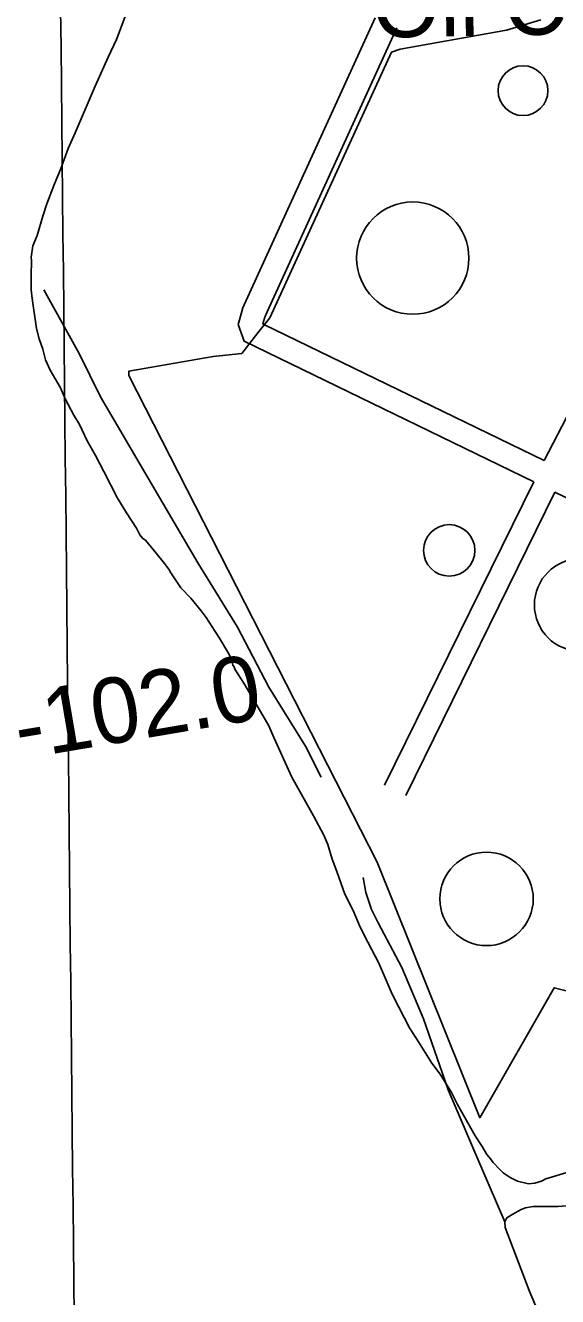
# Model space of a CAD drawing. Extents: x 3625074 to 3663148, y 511451 to 537151.
# Drawn here: x 3655631 to 3656305, y 518099 to 519708 of the extents above; entities that cross this region are included whole.
import ezdxf

# ---------------------------------------------------------------- set-up
doc = ezdxf.new("R2010")
doc.units = 0
for name, color, linetype in [('V-BLDG-IDEN', 7, 'Continuous'), ('V-DOMW-TANK', 7, 'Continuous'), ('V-GRID-MAJR', 7, 'Continuous'), ('V-RIVR-RANG-IDEN', 7, 'Continuous'), ('V-ROAD-CNTR', 7, 'Continuous'), ('V-SITE-OTLN', 7, 'Continuous'), ('V-SITE-VEGE', 7, 'Continuous'), ('V-TOPO-SHOR', 7, 'Continuous')]:
    doc.layers.add(name, color=color, linetype=linetype)

msp = doc.modelspace()

# ---------------------------------------------------------------- linework, layer by layer
at = {"layer": 'V-DOMW-TANK'}
for centre, radius in [((3656260.8533878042, 519625.75441761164), 31.546175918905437), ((3656121.260359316, 519413.65974637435), 71.10281345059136), ((3656167.4155102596, 519043.55996418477), 32.58380201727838), ((3656334.055766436, 518974.54792726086), 58.795414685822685), ((3656214.6349138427, 518602.2098070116), 59.181858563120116)]:
    msp.add_circle(centre, radius, dxfattribs=at)
at = {"layer": 'V-GRID-MAJR'}
msp.add_spline([(3655702.349, 517124.989), (3655639.7800000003, 523183.706), (3655577.191, 529244.355), (3655514.6010000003, 535305.018), (3655514.5810000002, 535306.936)], degree=3, dxfattribs=at)
at = {"layer": 'V-ROAD-CNTR'}
for points in [[(3655905.873, 519349.808), (3656073.653, 519717.962)], [(3655936.9050000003, 519345.561), (3656100.951, 519705.522)], [(3656287.5700000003, 519157.31200000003), (3656400.1684689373, 519374.43589152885), (3656417.7275075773, 519374.50241756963)], [(3656274.34, 519130.387), (3655907.691, 519308.363), (3655900.017, 519329.52400000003), (3655905.589, 519349.185), (3655905.873, 519349.808)], [(3656287.571, 519157.313), (3655931.7430000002, 519330.03500000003), (3655931.519, 519330.65400000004), (3655933.8310000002, 519338.815), (3655936.9050000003, 519345.561)], [(3656085.5700000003, 518746.238), (3656274.339, 519130.38800000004)], [(3656112.494, 518733.00800000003), (3656301.328, 519117.287)], [(3656531.8680000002, 519005.38), (3656301.328, 519117.287)]]:
    msp.add_lwpolyline(points, dxfattribs=at)
at = {"layer": 'V-SITE-OTLN'}
msp.add_lwpolyline([(3657238.198, 519920.066), (3657108.16, 519613.574), (3657087.029, 519593.178), (3657053.732, 519589.613), (3656946.394, 519627.511), (3656383.164, 518471.54600000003), (3656383.117, 518468.77900000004), (3656300.4020000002, 518489.626), (3656206.106, 518325.128), (3656076.1210000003, 518648.675), (3655761.606, 519264.886), (3655761.704, 519270.424), (3655868.659, 519289.304), (3655904.724, 519292.82), (3655925.286, 519318.99), (3655940.1380000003, 519337.891), (3656094.248, 519674.418), (3656105.396, 519678.375), (3656240.136, 519702.304), (3656283.291, 519715.38800000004)], dxfattribs=at)
at = {"layer": 'V-SITE-VEGE'}
for p, q in [((3655757.293, 519719.531), (3655746.148, 519690.42100000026)), ((3655746.148, 519690.42100000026), (3655735.648, 519668.3540000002)), ((3655735.648, 519668.3540000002), (3655719.1920000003, 519631.33)), ((3655719.1920000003, 519631.33), (3655693.7970000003, 519572.272)), ((3655693.7970000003, 519572.272), (3655684.81, 519552.574)), ((3655684.81, 519552.574), (3655675.182, 519525.8380000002)), ((3655675.182, 519525.8380000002), (3655667.728, 519507.731)), ((3655667.728, 519507.731), (3655658.0670000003, 519482.555)), ((3655658.0670000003, 519482.555), (3655652.91, 519466.83900000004)), ((3655652.91, 519466.83900000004), (3655645.577, 519442.488)), ((3655645.577, 519442.488), (3655640.373, 519429.113)), ((3655640.373, 519429.113), (3655638.304, 519415.016)), ((3655638.396, 519410.3330000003), (3655637.985, 519391.5830000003)), ((3655638.304, 519415.016), (3655638.396, 519410.3330000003)), ((3655637.985, 519391.5830000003), (3655638.333, 519373.6320000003)), ((3655638.333, 519373.6320000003), (3655639.326, 519362.719)), ((3655639.326, 519362.719), (3655644.757, 519324.56400000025)), ((3655644.757, 519324.56400000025), (3655648.139, 519311.35500000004)), ((3655648.139, 519311.35500000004), (3655653.08, 519298.17800000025)), ((3655653.08, 519298.17800000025), (3655656.464, 519284.968)), ((3655656.464, 519284.968), (3655662.186, 519271.806)), ((3655662.186, 519271.806), (3655675.117, 519249.413)), ((3655675.117, 519249.413), (3655681.65, 519234.706)), ((3655681.65, 519234.706), (3655692.1950000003, 519214.609)), ((3655692.1950000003, 519214.609), (3655699.449, 519203.03800000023)), ((3655699.449, 519203.03800000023), (3655709.2260000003, 519182.147)), ((3655709.2260000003, 519182.147), (3655719.741, 519163.612)), ((3655719.741, 519163.612), (3655730.284, 519143.515)), ((3655730.284, 519143.515), (3655747.348, 519109.49200000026)), ((3655747.348, 519109.49200000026), (3655758.6410000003, 519090.972)), ((3655758.6410000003, 519090.972), (3655771.5100000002, 519071.70400000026)), ((3655771.5100000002, 519071.70400000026), (3655775.582, 519063.193)), ((3655775.582, 519063.193), (3655779.575, 519058.585)), ((3655779.575, 519058.585), (3655782.7430000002, 519056.303)), ((3655782.7430000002, 519056.303), (3655796.3340000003, 519040.17300000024)), ((3655796.3340000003, 519040.17300000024), (3655806.74, 519027.101)), ((3655806.74, 519027.101), (3655813.1520000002, 519018.636)), ((3655813.1520000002, 519018.636), (3655813.977, 519016.31000000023)), ((3655813.977, 519016.31000000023), (3655827.644, 518996.27400000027)), ((3655827.644, 518996.27400000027), (3655840.393, 518983.251)), ((3655840.393, 518983.251), (3655853.201, 518967.10200000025)), ((3655853.201, 518967.10200000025), (3655859.613, 518958.63800000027)), ((3655859.613, 518958.63800000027), (3655870.8910000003, 518940.8980000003)), ((3655870.8910000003, 518940.8980000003), (3655876.523, 518932.4200000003)), ((3655876.523, 518932.4200000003), (3655887.021, 518914.66500000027)), ((3655887.021, 518914.66500000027), (3655891.873, 518906.1700000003)), ((3655891.873, 518906.1700000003), (3655893.585, 518898.39400000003)), ((3655893.585, 518898.39400000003), (3655895.193, 518896.08400000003)), ((3655895.193, 518896.08400000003), (3655896.035, 518892.977)), ((3655896.035, 518892.977), (3655907.313, 518875.237)), ((3655907.313, 518875.237), (3655928.309, 518839.729)), ((3655928.309, 518839.729), (3655938.822, 518821.19500000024)), ((3655938.822, 518821.19500000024), (3655945.357, 518806.48600000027)), ((3655945.357, 518806.48600000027), (3655968.202, 518756.17700000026)), ((3655968.202, 518756.17700000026), (3655986.001, 518724.509)), ((3655986.001, 518724.509), (3655995.703, 518707.52)), ((3655995.703, 518707.52), (3656008.681, 518682.78700000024)), ((3656008.681, 518682.78700000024), (3656013.592, 518671.17100000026)), ((3656013.592, 518671.17100000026), (3656019.423, 518652.54600000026)), ((3656019.423, 518652.54600000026), (3656025.1920000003, 518637.039)), ((3656025.1920000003, 518637.039), (3656035.123, 518608.34200000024)), ((3656035.123, 518608.34200000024), (3656045.68, 518587.46500000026)), ((3656045.68, 518587.46500000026), (3656054.679, 518566.55700000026)), ((3656054.679, 518566.55700000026), (3656064.4250000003, 518547.228)), ((3656064.4250000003, 518547.228), (3656078.215, 518520.94800000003)), ((3656078.215, 518520.94800000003), (3656086.386, 518502.3660000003)), ((3656086.386, 518502.3660000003), (3656095.3850000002, 518481.4580000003)), ((3656095.3850000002, 518481.4580000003), (3656103.509, 518465.22000000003)), ((3656103.509, 518465.22000000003), (3656117.2970000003, 518438.938)), ((3656117.2970000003, 518438.938), (3656128.577, 518421.202)), ((3656128.577, 518421.202), (3656145.502, 518394.201)), ((3656145.502, 518394.201), (3656155.924, 518380.35000000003)), ((3656155.924, 518380.35000000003), (3656170.432, 518357.208)), ((3656170.432, 518357.208), (3656177.762, 518341.733)), ((3656177.762, 518341.733), (3656200.394, 518302.352)), ((3656200.394, 518302.352), (3656209.254, 518288.47100000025)), ((3656209.254, 518288.47100000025), (3656214.916, 518278.43200000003)), ((3656214.916, 518278.43200000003), (3656219.707, 518273.058)), ((3656219.707, 518273.058), (3656222.92, 518268.43500000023)), ((3656222.92, 518268.43500000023), (3656230.895, 518260.00200000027)), ((3656230.895, 518260.00200000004), (3656235.669, 518255.41000000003)), ((3656235.669, 518255.41000000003), (3656244.377, 518249.33400000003)), ((3656244.377, 518249.33400000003), (3656253.835, 518244.83400000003)), ((3656284.292, 518244.6480000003), (3656289.693, 518247.878)), ((3656289.693, 518247.878), (3656320.7490000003, 518257.07300000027)), ((3656253.835, 518244.83400000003), (3656267.9620000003, 518241.205)), ((3656267.9620000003, 518241.20500000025), (3656275.75, 518242.1370000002)), ((3656275.75, 518242.137), (3656284.292, 518244.64799999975))]:
    msp.add_line(p, q, dxfattribs=at)
at = {"layer": 'V-TOPO-SHOR'}
for points in [[(3656005.435, 518756.48000000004), (3655985.375, 518795.478), (3655938.887, 518870.13800000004), (3655899.2090000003, 518946.135), (3655848.963, 519027.955), (3655793.235, 519122.933), (3655725.8540000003, 519238.184), (3655699.056, 519292.726), (3655654.059, 519373.444)], [(3656237.973, 518193.458), (3656208.512, 518260.813), (3656165.957, 518360.47000000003), (3656134.85, 518450.304), (3656107.446, 518515.287), (3656077.395, 518571.777), (3656069.019, 518588.898), (3656061.7630000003, 518610.46400000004), (3656058.578, 518629.293)], [(3656355.159, 518223.494), (3656331.186, 518216.191), (3656320.778, 518213.97500000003), (3656305.524, 518212.873), (3656290.6580000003, 518212.58), (3656273.774, 518212.652), (3656264.161, 518210.856), (3656258.576, 518208.734), (3656247.836, 518202.897), (3656240.287, 518198.326), (3656237.973, 518193.458), (3656238.114, 518186.22500000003), (3656268.6210000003, 518106.43), (3656281.276, 518076.128)]]:
    msp.add_lwpolyline(points, dxfattribs=at)

# ---------------------------------------------------------------- texts
at = {"layer": 'V-BLDG-IDEN'}
msp.add_text('Oil Co.', height=82.99983200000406, rotation=1.0368000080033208, dxfattribs=at).set_placement((3656070.171820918, 519692.76958826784))
at = {"layer": 'V-RIVR-RANG-IDEN'}
msp.add_text('R-102.0', height=82.999998, rotation=9.635688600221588, dxfattribs=at).set_placement((3655544.6210000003, 518765.231))

doc.saveas('drawing.dxf')
